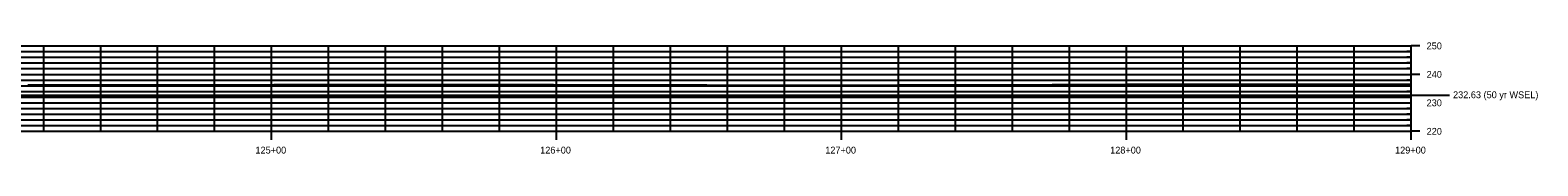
# Model space of a CAD drawing. Extents: x 1676565 to 1681112, y 227357 to 229815.
# Drawn here: x 1680583 to 1681112, y 229581 to 229620 of the extents above; entities that cross this region are included whole.
import ezdxf

# ---------------------------------------------------------------- set-up
doc = ezdxf.new("R2010")
doc.units = 0
for name, color, linetype in [('R_Axis', 7, 'Continuous'), ('R_Axis Annot', 7, 'Continuous'), ('R_Exist Surface', 7, 'Continuous'), ('R_Grid', 7, 'Continuous'), ('R_Water', 7, 'Continuous')]:
    doc.layers.add(name, color=color, linetype=linetype)

msp = doc.modelspace()

# ---------------------------------------------------------------- linework, layer by layer
at = {"layer": 'R_Axis'}
for p, q in [((1681067.31, 229588.83), (1681067.31, 229618.83)), ((1678167.31, 229588.83), (1681067.31, 229588.83))]:
    msp.add_line(p, q, dxfattribs=at)
at = {"layer": 'R_Exist Surface'}
msp.add_lwpolyline([(1680581.73, 229605.16), (1680596.3, 229605.16), (1680596.58, 229605.16), (1680611.23, 229605.16), (1680611.43, 229605.16), (1680626.16, 229605.16), (1680641.04, 229605.17), (1680641.08, 229605.17), (1680654.57, 229605.19), (1680654.59, 229605.19), (1680668.09, 229605.21), (1680668.1, 229605.21), (1680677.12, 229605.22), (1680681.61, 229605.23), (1680681.61, 229605.23), (1680695.12, 229605.25), (1680695.14, 229605.25), (1680698.18, 229605.25), (1680709.39, 229605.25), (1680709.46, 229605.25), (1680723.64, 229605.25), (1680723.79, 229605.25), (1680737.89, 229605.25), (1680738.13, 229605.25), (1680738.37, 229605.25), (1680752.47, 229605.25), (1680765.72, 229605.22), (1680765.98, 229605.22), (1680766.24, 229605.22), (1680779.49, 229605.18), (1680779.69, 229605.18), (1680793, 229605.15), (1680793.15, 229605.15), (1680806.51, 229605.12), (1680806.6, 229605.12), (1680819.83, 229605.1), (1680820.03, 229605.1), (1680833.15, 229605.09), (1680833.44, 229605.09), (1680846.47, 229605.07), (1680846.86, 229605.07), (1680859.78, 229605.06), (1680860.3, 229605.06), (1680873.56, 229605.08), (1680874.09, 229605.08), (1680887.35, 229605.1), (1680887.87, 229605.1), (1680901.14, 229605.13), (1680914.42, 229605.15), (1680914.93, 229605.15), (1680927.61, 229605.19), (1680928.08, 229605.19), (1680928.55, 229605.19), (1680941.24, 229605.24), (1680941.71, 229605.24), (1680954.39, 229605.28), (1680954.87, 229605.28), (1680967.54, 229605.33), (1680968.1, 229605.33), (1680982.17, 229605.34), (1680982.76, 229605.34), (1680996.8, 229605.35), (1681010.8, 229605.35), (1681011.44, 229605.35), (1681025.41, 229605.36), (1681026.07, 229605.36), (1681046.46, 229605.37), (1681047.43, 229605.37), (1681067.31, 229605.38)], dxfattribs=at)
at = {"layer": 'R_Grid'}
for p, q in [((1678167.31, 229618.83), (1681067.31, 229618.83)), ((1678167.31, 229618.83), (1681067.31, 229618.83)), ((1678167.31, 229616.83), (1681067.31, 229616.83)), ((1680587.31, 229588.83), (1680587.31, 229618.83)), ((1680607.31, 229588.83), (1680607.31, 229618.83)), ((1680627.31, 229588.83), (1680627.31, 229618.83)), ((1680647.31, 229588.83), (1680647.31, 229618.83)), ((1680667.31, 229588.83), (1680667.31, 229618.83)), ((1680687.31, 229588.83), (1680687.31, 229618.83)), ((1680707.31, 229588.83), (1680707.31, 229618.83)), ((1680727.31, 229588.83), (1680727.31, 229618.83)), ((1680747.31, 229588.83), (1680747.31, 229618.83)), ((1680767.31, 229588.83), (1680767.31, 229618.83)), ((1680787.31, 229588.83), (1680787.31, 229618.83)), ((1680807.31, 229588.83), (1680807.31, 229618.83)), ((1680827.31, 229588.83), (1680827.31, 229618.83)), ((1680847.31, 229588.83), (1680847.31, 229618.83)), ((1680867.31, 229588.83), (1680867.31, 229618.83)), ((1680887.31, 229588.83), (1680887.31, 229618.83)), ((1680907.31, 229588.83), (1680907.31, 229618.83)), ((1680927.31, 229588.83), (1680927.31, 229618.83)), ((1680947.31, 229588.83), (1680947.31, 229618.83)), ((1680967.31, 229588.83), (1680967.31, 229618.83)), ((1680987.31, 229588.83), (1680987.31, 229618.83)), ((1681007.31, 229588.83), (1681007.31, 229618.83)), ((1681027.31, 229588.83), (1681027.31, 229618.83)), ((1681047.31, 229588.83), (1681047.31, 229618.83)), ((1681067.31, 229616.83), (1681065.81, 229616.83)), ((1681070.31, 229618.83), (1681067.31, 229618.83)), ((1681070.31, 229618.83), (1681067.31, 229618.83)), ((1678167.31, 229614.83), (1681067.31, 229614.83)), ((1678167.31, 229612.83), (1681067.31, 229612.83)), ((1678167.31, 229610.83), (1681067.31, 229610.83)), ((1681067.31, 229614.83), (1681065.81, 229614.83)), ((1681067.31, 229612.83), (1681065.81, 229612.83)), ((1681067.31, 229610.83), (1681065.81, 229610.83)), ((1678167.31, 229608.83), (1681067.31, 229608.83)), ((1678167.31, 229606.83), (1681067.31, 229606.83)), ((1678167.31, 229604.83), (1681067.31, 229604.83)), ((1681067.31, 229606.83), (1681065.81, 229606.83)), ((1681067.31, 229604.83), (1681065.81, 229604.83)), ((1681070.31, 229608.83), (1681067.31, 229608.83)), ((1678167.31, 229602.83), (1681067.31, 229602.83)), ((1678167.31, 229600.83), (1681067.31, 229600.83)), ((1681067.31, 229602.83), (1681065.81, 229602.83)), ((1681067.31, 229600.83), (1681065.81, 229600.83)), ((1678167.31, 229598.83), (1681067.31, 229598.83)), ((1678167.31, 229596.83), (1681067.31, 229596.83)), ((1678167.31, 229594.83), (1681067.31, 229594.83)), ((1681067.31, 229596.83), (1681065.81, 229596.83)), ((1681067.31, 229594.83), (1681065.81, 229594.83)), ((1678167.31, 229592.83), (1681067.31, 229592.83)), ((1678167.31, 229590.83), (1681067.31, 229590.83)), ((1680667.31, 229585.83), (1680667.31, 229588.83)), ((1680767.31, 229585.83), (1680767.31, 229588.83)), ((1680867.31, 229585.83), (1680867.31, 229588.83)), ((1680967.31, 229585.83), (1680967.31, 229588.83)), ((1681067.31, 229592.83), (1681065.81, 229592.83)), ((1681067.31, 229590.83), (1681065.81, 229590.83)), ((1681070.31, 229588.83), (1681067.31, 229588.83)), ((1681067.31, 229585.83), (1681067.31, 229588.83))]:
    msp.add_line(p, q, dxfattribs=at)
at = {"layer": 'R_Water'}
msp.add_line((1681080.69, 229601.46), (1678154.35, 229601.46), dxfattribs=at)

# ---------------------------------------------------------------- texts
at = {"layer": 'R_Axis Annot'}
for s, p in [('250', (1681072.71, 229617.63)), ('250', (1681072.71, 229617.63)), ('240', (1681072.71, 229607.63)), ('230', (1681072.71, 229597.63)), ('220', (1681072.71, 229587.63)), ('125+00', (1680661.63, 229581.03)), ('126+00', (1680761.57, 229581.03)), ('127+00', (1680861.63, 229581.03)), ('128+00', (1680961.63, 229581.03)), ('129+00', (1681061.63, 229581.03))]:
    msp.add_text(s, height=2.4, dxfattribs=at).set_placement(p)
at = {"layer": 'R_Water'}
msp.add_text('232.63 (50 yr WSEL)', height=2.4, dxfattribs=at).set_placement((1681081.98, 229600.46))

doc.saveas('drawing.dxf')
